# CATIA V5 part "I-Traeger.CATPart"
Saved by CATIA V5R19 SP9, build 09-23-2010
Part number: I-Traeger
Publications: "Hauptkörper"
Bounding box of the stored display mesh (mm): x -100 to 100, y 0 to 200, z 0 to 500
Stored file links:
  D:\Daten\CAD-Daten\Diverse Vorlagen\I-Träger\I-Traeger.CATPart
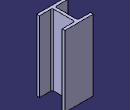
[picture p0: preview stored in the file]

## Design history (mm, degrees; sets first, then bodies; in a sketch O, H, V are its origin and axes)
AxisSystem1: origin (0, 0, 0), X (1, 0, 0), Y (0, 1, 0), Z (0, 0, 1)
Body1 (main body)
  Body2
    Body3
      Solid1: linked copy from another document
    Add1: tool Body3
    Body4
      Body5
        Solid2: linked copy from another document
        Thickness1: Thickness -20, Face (face of Solid2; face of Solid2)
      Add2: tool Body5
      Body6
        Solid3: linked copy from another document
      Remove1: tool Body6
      Fillet1: radius 10, on edge [face of Solid2 | face of Solid3] (x2); edge [face of Solid3 | face of Solid2] (x2)
    Remove2: tool Body4
  Add3: tool Body2
Body7 "Grundgeo"
  Body8
    Sketch1 on XY plane of AxisSystem1, origin (0, 0, 0), H (1, 0, 0), V (0, 1, 0)
      line L1 (-100, 200) -> (100, 200)
      line L2 (100, 200) -> (100, 0)
      line L3 (100, 0) -> (-100, 0)
      line L4 (-100, 0) -> (-100, 200)
      length L3 = 200
      length L2 = 200
      horizontal: L1 H, L3 H
      vertical: L2 V, L4 V
      symmetry: L2 L4 V
      coincidence: H L3
    Pad1: profile Sketch1, direction (0, 0, 1), length 500
  Add4: tool Body8
  Body9
    Sketch2 on XY plane of AxisSystem1, origin (0, 0, 0), H (1, 0, 0), V (0, 1, 0)
      line L1 (-10, 200) -> (10, 200)
      line L2 (10, 200) -> (10, 0)
      line L3 (10, 0) -> (-10, 0)
      line L4 (-10, 0) -> (-10, 200)
      length L3 = 20
      length L2 = 200
      horizontal: L1 H, L3 H
      vertical: L2 V, L4 V
      symmetry: L2 L4 V
      coincidence: H L3
    Pad2: profile Sketch2, direction (0, 0, 1), length 500
  Add5: tool Body9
